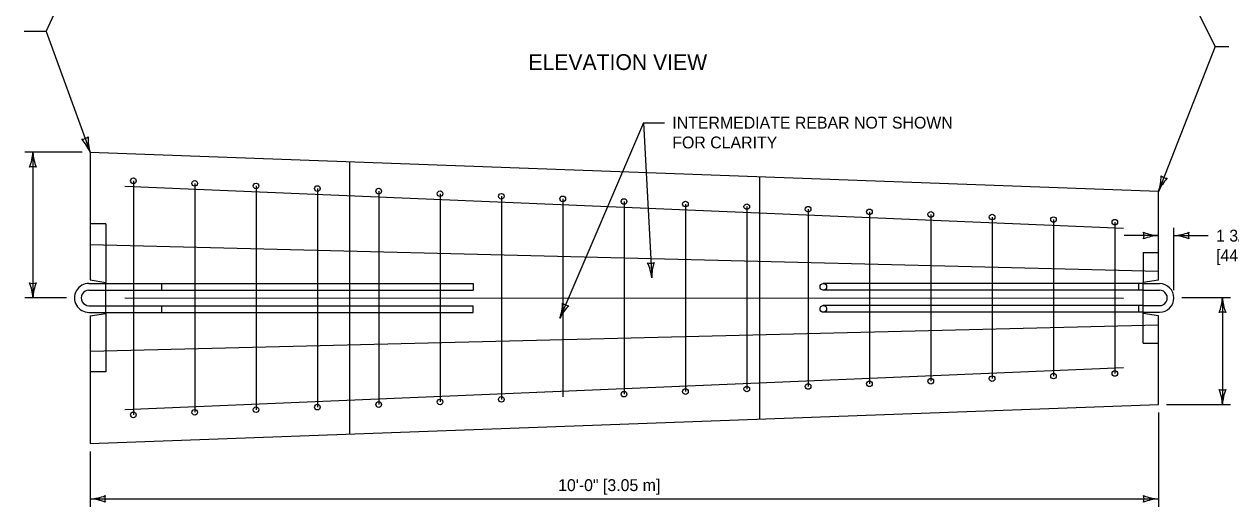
# Model space of a CAD drawing. Extents: x 49991.4 to 50021, y 49987.6 to 50011.4.
# Drawn here: x 50003.53 to 50009.63, y 49991.71 to 49994.15 of the extents above; entities that cross this region are included whole.
import ezdxf

# ---------------------------------------------------------------- set-up
doc = ezdxf.new("R2010")
doc.units = 0
for name, color, linetype in [('Level 1', 7, 'Continuous'), ('Level 2', 7, 'Continuous'), ('Level 3', 7, 'Continuous'), ('Level 4', 7, 'Continuous')]:
    doc.layers.add(name, color=color, linetype=linetype)

msp = doc.modelspace()

# ---------------------------------------------------------------- linework, layer by layer
at = {"layer": 'Level 1'}
for p, q in [((50003.8623, 49993.5059), (50003.8623, 49992.8598)), ((50003.8623, 49993.5059), (50009.2624, 49993.3091)), ((50004.0808, 49993.3613), (50004.0808, 49992.1775)), ((50004.0374, 49993.3348), (50009.0846, 49993.1217)), ((50004.3908, 49993.3483), (50004.3908, 49992.1905)), ((50004.7008, 49993.3352), (50004.7008, 49992.2036)), ((50005.0108, 49993.3221), (50005.0108, 49992.2167)), ((50005.3208, 49993.309), (50005.3208, 49992.2298)), ((50005.6308, 49993.2959), (50005.6308, 49992.2429)), ((50009.2624, 49992.8589), (50009.2624, 49993.3091)), ((50005.9408, 49993.2828), (50005.9408, 49992.256)), ((50006.2509, 49993.2698), (50006.2509, 49992.2691)), ((50006.5609, 49993.2567), (50006.5609, 49992.2822)), ((50006.8709, 49993.2436), (50006.8709, 49992.2953)), ((50007.1809, 49993.2305), (50007.1809, 49992.3083)), ((50007.4909, 49993.2174), (50007.4909, 49992.3214)), ((50007.8009, 49993.2043), (50007.8009, 49992.3345)), ((50008.1109, 49993.1912), (50008.1109, 49992.3476)), ((50008.4209, 49993.1781), (50008.4209, 49992.3607)), ((50008.731, 49993.165), (50008.731, 49992.3738)), ((50009.041, 49993.1519), (50009.041, 49992.3869)), ((50003.8623, 49993.039), (50009.2624, 49992.9042)), ((50003.8564, 49992.8426), (50003.9414, 49992.8423)), ((50003.8564, 49992.8084), (50003.9414, 49992.8083)), ((50003.8623, 49992.8598), (50003.9414, 49992.8477)), ((50003.9414, 49992.6904), (50003.9414, 49992.8477)), ((50009.2624, 49992.8589), (50009.1834, 49992.8468)), ((50009.1834, 49992.691), (50009.1834, 49992.8468)), ((50009.1834, 49992.8415), (50009.2668, 49992.8415)), ((50009.1834, 49992.8079), (50009.2668, 49992.8079)), ((50004.0374, 49992.7694), (50009.0846, 49992.7683)), ((50003.8564, 49992.7296), (50003.9414, 49992.7293)), ((50003.8564, 49992.6957), (50003.9414, 49992.6956)), ((50003.8623, 49992.678), (50003.9414, 49992.6904)), ((50009.1834, 49992.7299), (50009.2668, 49992.7299)), ((50009.1834, 49992.6963), (50009.2668, 49992.6963)), ((50009.2624, 49992.6789), (50009.1834, 49992.691)), ((50003.8623, 49992.678), (50003.8623, 49992.0323)), ((50003.8623, 49992.4992), (50009.2624, 49992.6323)), ((50009.2624, 49992.2298), (50009.2624, 49992.6789)), ((50004.0374, 49992.204), (50009.0846, 49992.4171)), ((50003.8623, 49992.0323), (50009.2624, 49992.2298))]:
    msp.add_line(p, q, dxfattribs=at)
for centre in [(50004.0808, 49993.3613), (50004.3908, 49993.3483), (50004.7008, 49993.3352), (50005.0108, 49993.3221), (50005.3208, 49993.309), (50005.6308, 49993.2959), (50005.9408, 49993.2828), (50006.2509, 49993.2698), (50006.5608, 49993.2566), (50006.8709, 49993.2436), (50007.1809, 49993.2305), (50007.4909, 49993.2174), (50007.8009, 49993.2043), (50008.1109, 49993.1912), (50008.4209, 49993.1781), (50008.731, 49993.165), (50009.041, 49993.1519), (50008.731, 49992.3738), (50009.041, 49992.3869), (50007.1809, 49992.3083), (50007.4909, 49992.3214), (50007.8009, 49992.3345), (50008.1109, 49992.3476), (50008.4209, 49992.3607), (50005.6308, 49992.2429), (50005.9408, 49992.256), (50006.5608, 49992.2822), (50006.8709, 49992.2953), (50004.3908, 49992.1905), (50004.7008, 49992.2036), (50005.0108, 49992.2167), (50005.3208, 49992.2298), (50004.0808, 49992.1775)]:
    msp.add_circle(centre, 0.0142, dxfattribs=at)
for centre, radius, start, end in [((50003.8563, 49992.7691), 0.0734, 89.97748, 270.02252), ((50003.8564, 49992.769), 0.0394, 89.99436, 270.00564), ((50009.2666, 49992.7689), 0.0726, 270.22156, 89.77843), ((50009.2671, 49992.7689), 0.039, 269.64135, 90.35864)]:
    msp.add_arc(centre, radius, start, end, dxfattribs=at)
at = {"layer": 'Level 3'}
for p, q in [((50003.6395, 49994.1166), (50003.8642, 49994.6042)), ((50009.2642, 49994.6042), (50009.548, 49994.0405)), ((50003.6395, 49994.1166), (50003.5288, 49994.1166)), ((50003.6395, 49994.1166), (50003.8623, 49993.5059)), ((50009.548, 49994.0405), (50009.2624, 49993.3091)), ((50009.548, 49994.0405), (50009.618, 49994.0405)), ((50006.6587, 49993.6552), (50006.2359, 49992.6658)), ((50006.6587, 49993.6552), (50006.7645, 49993.6552)), ((50006.6587, 49993.6552), (50006.7005, 49992.8711)), ((50003.8223, 49993.506), (50003.533, 49993.506)), ((50003.573, 49993.506), (50003.573, 49992.7693)), ((50009.3392, 49992.8089), (50009.3392, 49993.1239)), ((50009.2624, 49993.084), (50009.089, 49993.084)), ((50009.3392, 49993.0839), (50009.5126, 49993.0839)), ((50003.7429, 49992.7693), (50003.533, 49992.7693)), ((50009.3791, 49992.7705), (50009.6249, 49992.7705)), ((50009.5849, 49992.7705), (50009.5849, 49992.2302)), ((50009.3024, 49992.2302), (50009.6249, 49992.2302)), ((50009.2624, 49992.1898), (50009.2624, 49991.7122)), ((50003.8624, 49991.9923), (50003.8624, 49991.7122)), ((50003.8624, 49991.7522), (50009.2624, 49991.7522))]:
    msp.add_line(p, q, dxfattribs=at)
for centre, radius, start, end in [((50003.8184, 49993.6263), 0.0548, 272.17709, 307.89945), ((50003.6476, 49993.4153), 0.233, 22.86558, 42.11543), ((50004.0741, 49993.5734), 0.2223, 177.49428, 197.67779), ((50003.3509, 49993.5151), 0.2223, 337.45601, 357.63952), ((50003.8057, 49993.5175), 0.233, 182.82731, 202.07716), ((50003.573, 49993.3778), 0.0548, 72.13882, 107.86118), ((50009.0415, 49993.3831), 0.233, 341.4844, 0.73425), ((50009.466, 49993.2197), 0.2223, 136.1131, 156.29661), ((50009.3091, 49993.4285), 0.0548, 230.79591, 266.51827), ((50009.2716, 49993.3061), 0.2223, 247.45601, 267.63952), ((50009.1342, 49993.084), 0.0548, 342.13882, 17.86118), ((50009.2739, 49992.8513), 0.233, 92.82731, 112.07716), ((50009.3277, 49993.3166), 0.233, 272.82731, 292.07716), ((50009.33, 49992.8618), 0.2223, 67.45601, 87.63952), ((50009.4674, 49993.0839), 0.0548, 162.13882, 197.86118), ((50006.6937, 49992.9991), 0.0548, 255.19261, 290.91497), ((50006.4688, 49992.8472), 0.233, 5.8811, 25.13095), ((50006.9228, 49992.8738), 0.2223, 160.5098, 180.69331), ((50003.573, 49992.8975), 0.0548, 252.13882, 287.86118), ((50003.3403, 49992.7578), 0.233, 2.82731, 22.07716), ((50003.7951, 49992.7601), 0.2223, 157.45601, 177.63952), ((50006.0174, 49992.7467), 0.233, 339.68852, 358.93837), ((50006.2863, 49992.7837), 0.0548, 229.00003, 264.72239), ((50009.3628, 49992.7797), 0.2223, 337.45601, 357.63952), ((50009.8176, 49992.782), 0.233, 182.82731, 202.07716), ((50006.4366, 49992.5701), 0.2223, 134.31722, 154.50073), ((50009.5849, 49992.6423), 0.0548, 72.13882, 107.86118), ((50009.5849, 49992.3585), 0.0548, 252.13882, 287.86118), ((50009.3522, 49992.2187), 0.233, 2.82731, 22.07716), ((50009.807, 49992.2211), 0.2223, 157.45601, 177.63952), ((50003.8509, 49991.9849), 0.233, 272.82731, 292.07716), ((50003.9906, 49991.7522), 0.0548, 162.13882, 197.86118), ((50009.2716, 49991.9743), 0.2223, 247.45601, 267.63952), ((50009.1342, 49991.7522), 0.0548, 342.13882, 17.86118), ((50003.8532, 49991.5301), 0.2223, 67.45601, 87.63952), ((50009.2739, 49991.5195), 0.233, 92.82731, 112.07716)]:
    msp.add_arc(centre, radius, start, end, dxfattribs=at)
at = {"layer": 'Level 4'}
for p, q in [((50005.1751, 49992.0803), (50005.1751, 49993.458)), ((50007.2474, 49992.1561), (50007.2474, 49993.3825)), ((50003.9414, 49993.1436), (50003.8623, 49993.1436)), ((50003.9414, 49993.1436), (50003.9414, 49992.8477)), ((50009.1834, 49992.9983), (50009.2624, 49992.9983)), ((50009.1834, 49992.9983), (50009.1834, 49992.8468)), ((50003.9414, 49992.8423), (50005.7988, 49992.8423)), ((50003.9414, 49992.8083), (50005.7988, 49992.8083)), ((50004.2251, 49992.8083), (50004.2251, 49992.8423)), ((50005.7988, 49992.8423), (50005.7988, 49992.8083)), ((50009.1834, 49992.8415), (50007.5678, 49992.8415)), ((50009.1834, 49992.8079), (50007.5678, 49992.8079)), ((50009.1623, 49992.8079), (50009.1623, 49992.8415)), ((50003.9414, 49992.7293), (50005.7988, 49992.7293)), ((50003.9414, 49992.6956), (50005.7988, 49992.6956)), ((50003.9414, 49992.6904), (50003.9414, 49992.3948)), ((50004.2251, 49992.6956), (50004.2251, 49992.7293)), ((50005.7988, 49992.6956), (50005.7988, 49992.7293)), ((50009.1834, 49992.7299), (50007.5678, 49992.7299)), ((50009.1834, 49992.6963), (50007.5678, 49992.6963)), ((50009.1623, 49992.6963), (50009.1623, 49992.7299)), ((50009.1834, 49992.5397), (50009.1834, 49992.691)), ((50009.1834, 49992.5397), (50009.2624, 49992.5397)), ((50003.9414, 49992.3948), (50003.8623, 49992.3948))]:
    msp.add_line(p, q, dxfattribs=at)
for centre in [(50007.5678, 49992.8247), (50007.5678, 49992.7131)]:
    msp.add_circle(centre, 0.0168, dxfattribs=at)

# ---------------------------------------------------------------- texts
at = {"layer": 'Level 2'}
for s, height, p in [('ELEVATION VIEW', 0.08, (50006.0772, 49993.9216)), ('INTERMEDIATE REBAR NOT SHOWN', 0.06, (50006.8045, 49993.6252)), ('FOR CLARITY', 0.06, (50006.8045, 49993.5252)), ('1 3/4" (±1/8")', 0.06, (50009.5526, 49993.0539)), ('[44 (±3)]', 0.06, (50009.5526, 49992.9539)), ('10\'-0" [3.05 m]', 0.06, (50006.2275, 49991.7922))]:
    msp.add_text(s, height=height, dxfattribs=at).set_placement(p)

doc.saveas('drawing.dxf')
